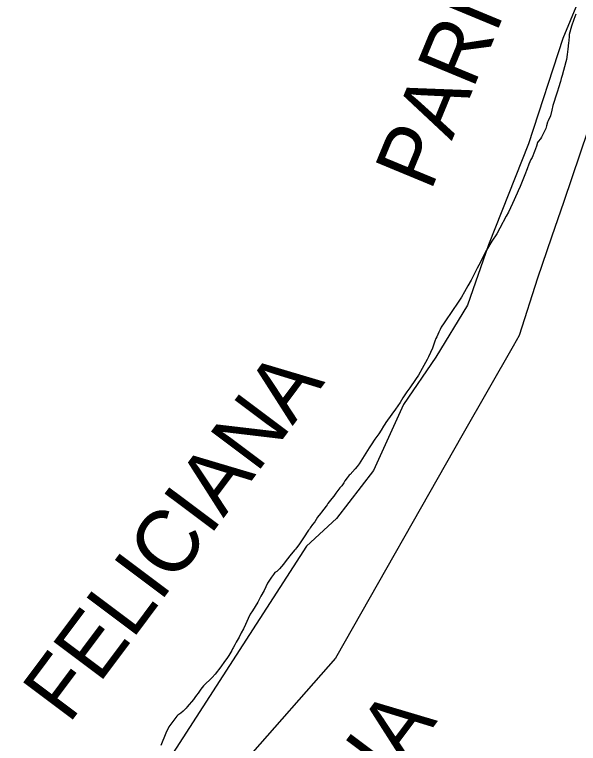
# Model space of a CAD drawing. Extents: x 3177385 to 3215275, y 903885 to 929304.
# Drawn here: x 3182527 to 3183436, y 916526 to 917702 of the extents above; entities that cross this region are included whole.
import ezdxf

# ---------------------------------------------------------------- set-up
doc = ezdxf.new("R2010")
doc.units = 0
for name, color, linetype in [('V-SITE-VEGE', 7, 'Continuous'), ('V-TOPO-BNDY', 7, 'Continuous'), ('V-TOPO-GNAM-IDEN', 7, 'Continuous'), ('V-TOPO-SHOR', 7, 'Continuous')]:
    doc.layers.add(name, color=color, linetype=linetype)

msp = doc.modelspace()

# ---------------------------------------------------------------- linework, layer by layer
at = {"layer": 'V-SITE-VEGE'}
for p, q in [((3183428.9, 917693.5), (3183425.2, 917682.7)), ((3183431.8, 917702.3), (3183428.9, 917693.5)), ((3183425.2, 917682.7), (3183421.4, 917669.5)), ((3183421.4, 917669.5), (3183421, 917666.7)), ((3183420.4, 917656.3), (3183419.1, 917645.9)), ((3183420.5, 917659.1), (3183420.4, 917656.3)), ((3183421, 917666.7), (3183420.5, 917659.1)), ((3183419.1, 917645.9), (3183417.8, 917637.1)), ((3183417.8, 917637.1), (3183416.9, 917629.1)), ((3183416, 917625.5), (3183410.2, 917603.5)), ((3183416.9, 917629.1), (3183416, 917625.5)), ((3183408.5, 917598.7), (3183407.2, 917593.9)), ((3183410.2, 917603.5), (3183408.5, 917598.7)), ((3183407.2, 917593.9), (3183403.9, 917583.5)), ((3183401.4, 917574.8), (3183395.1, 917554.8)), ((3183402.6, 917578.3), (3183401.4, 917574.8)), ((3183403.9, 917583.5), (3183402.6, 917578.3)), ((3183395.1, 917554.8), (3183393.4, 917547.6)), ((3183390.9, 917538.4), (3183387.2, 917530.4)), ((3183393.4, 917547.6), (3183390.9, 917538.4)), ((3183386.4, 917528), (3183384.7, 917522)), ((3183387.2, 917530.4), (3183386.4, 917528)), ((3183383.4, 917518), (3183376.8, 917504.1)), ((3183384.7, 917522), (3183383.4, 917518)), ((3183376.8, 917504.1), (3183375.2, 917501.3)), ((3183370.3, 917495.4), (3183368.6, 917489.4)), ((3183371.5, 917496.9), (3183370.3, 917495.4)), ((3183375.2, 917501.3), (3183371.5, 917496.9)), ((3183365.3, 917480.6), (3183361.6, 917471.4)), ((3183368.6, 917489.4), (3183365.3, 917480.6)), ((3183359.5, 917467.8), (3183357.9, 917464.2)), ((3183361.6, 917471.4), (3183359.5, 917467.8)), ((3183356.2, 917460.2), (3183353.7, 917452.7)), ((3183357.9, 917464.2), (3183356.2, 917460.2)), ((3183353.7, 917452.7), (3183350, 917443.1)), ((3183350, 917443.1), (3183342.2, 917424.7)), ((3183342.2, 917424.7), (3183338.9, 917417.6)), ((3183337.2, 917413.6), (3183329.8, 917396.8)), ((3183338.9, 917417.6), (3183337.2, 917413.6)), ((3183329.8, 917396.8), (3183323.2, 917382.9)), ((3183319.5, 917376.5), (3183309.6, 917357.4)), ((3183323.2, 917382.9), (3183319.5, 917376.5)), ((3183309.6, 917357.4), (3183304.3, 917348.2)), ((3183304.3, 917348.2), (3183296.6, 917336.3)), ((3183296.6, 917336.3), (3183288, 917322)), ((3183288, 917322), (3183275.6, 917297.7)), ((3183273.1, 917292.5), (3183267.4, 917282.1)), ((3183275.6, 917297.7), (3183273.1, 917292.5)), ((3183267.4, 917282.1), (3183262.9, 917273.4)), ((3183262.9, 917273.4), (3183257.6, 917264.2)), ((3183257.6, 917264.2), (3183252.6, 917254.7)), ((3183247.3, 917245.9), (3183245.3, 917242.7)), ((3183252.6, 917254.7), (3183247.3, 917245.9)), ((3183242, 917238), (3183222, 917207.7)), ((3183245.3, 917242.7), (3183242, 917238)), ((3183215, 917197.8), (3183213.4, 917193.8)), ((3183219.5, 917204.6), (3183215, 917197.8)), ((3183222, 917207.7), (3183219.5, 917204.6)), ((3183210.9, 917189.8), (3183208, 917182.2)), ((3183213.4, 917193.8), (3183210.9, 917189.8)), ((3183204.7, 917175.1), (3183200.6, 917163.9)), ((3183206.4, 917179.1), (3183204.7, 917175.1)), ((3183208, 917182.2), (3183206.4, 917179.1)), ((3183200.6, 917163.9), (3183194.4, 917149.9)), ((3183192.3, 917145.6), (3183184.1, 917130.8)), ((3183194.4, 917149.9), (3183192.3, 917145.6)), ((3183184.1, 917130.8), (3183178, 917120.5)), ((3183178, 917120.5), (3183173.1, 917113.3)), ((3183173.1, 917113.3), (3183164.1, 917099.8)), ((3183159.2, 917093.1), (3183153.1, 917083.5)), ((3183164.1, 917099.8), (3183159.2, 917093.1)), ((3183151, 917079.9), (3183148.5, 917075.9)), ((3183153.1, 917083.5), (3183151, 917079.9)), ((3183148.5, 917075.9), (3183141.2, 917065.2)), ((3183135.1, 917057.3), (3183125.7, 917043.8)), ((3183141.2, 917065.2), (3183135.1, 917057.3)), ((3183122, 917038.2), (3183117.9, 917031.8)), ((3183124.1, 917041), (3183122, 917038.2)), ((3183125.7, 917043.8), (3183124.1, 917041)), ((3183114.2, 917025.9), (3183107.7, 917017.1)), ((3183117.9, 917031.8), (3183114.2, 917025.9)), ((3183107.7, 917017.1), (3183101.6, 917008)), ((3183098.7, 917003.2), (3183082.4, 916977.3)), ((3183101.6, 917008), (3183098.7, 917003.2)), ((3183082.4, 916977.3), (3183079.1, 916973)), ((3183076.2, 916969.4), (3183068.1, 916960.3)), ((3183079.1, 916973), (3183076.2, 916969.4)), ((3183063.2, 916954.7), (3183059.6, 916950)), ((3183064.5, 916957.1), (3183063.2, 916954.7)), ((3183066.1, 916959.1), (3183064.5, 916957.1)), ((3183068.1, 916960.3), (3183066.1, 916959.1)), ((3183054.7, 916942), (3183051.4, 916938.4)), ((3183057.5, 916946.4), (3183054.7, 916942)), ((3183059.6, 916950), (3183057.5, 916946.4)), ((3183044.9, 916930.1), (3183041.6, 916925.3)), ((3183051.4, 916938.4), (3183044.9, 916930.1)), ((3183034.3, 916915.8), (3183032.2, 916913.4)), ((3183038.4, 916921.4), (3183034.3, 916915.8)), ((3183041.6, 916925.3), (3183038.4, 916921.4)), ((3183029, 916909), (3183021.6, 916899.5)), ((3183030.6, 916911), (3183029, 916909)), ((3183032.2, 916913.4), (3183030.6, 916911)), ((3183020, 916897.1), (3183015.5, 916891.2)), ((3183021.6, 916899.5), (3183020, 916897.1)), ((3183011, 916884), (3183007.4, 916879.3)), ((3183015.5, 916891.2), (3183011, 916884)), ((3183000.8, 916870.1), (3182998.4, 916866.9)), ((3183002.1, 916872.1), (3183000.8, 916870.1)), ((3183003.7, 916874.1), (3183002.1, 916872.1)), ((3183007.4, 916879.3), (3183003.7, 916874.1)), ((3182995.1, 916861.4), (3182984.9, 916846.7)), ((3182998.4, 916866.9), (3182995.1, 916861.4)), ((3182984.9, 916846.7), (3182981.2, 916841.9)), ((3182978.4, 916838.3), (3182970.6, 916828.8)), ((3182980, 916839.9), (3182978.4, 916838.3)), ((3182981.2, 916841.9), (3182980, 916839.9)), ((3182970.6, 916828.8), (3182963.3, 916819.3)), ((3182960.5, 916815.3), (3182953.9, 916807.8)), ((3182963.3, 916819.3), (3182960.5, 916815.3)), ((3182944.2, 916798.7), (3182941.3, 916794.7)), ((3182945.4, 916800.6), (3182944.2, 916798.7)), ((3182946.7, 916802.2), (3182945.4, 916800.6)), ((3182949.5, 916803.8), (3182946.7, 916802.2)), ((3182951.1, 916805.4), (3182949.5, 916803.8)), ((3182953.9, 916807.8), (3182951.1, 916805.4)), ((3182941.3, 916794.7), (3182934.8, 916784.7)), ((3182934.8, 916784.7), (3182929.1, 916773.2)), ((3182923.7, 916764), (3182918.8, 916754.5)), ((3182929.1, 916773.2), (3182923.7, 916764)), ((3182918.8, 916754.5), (3182910.2, 916740.1)), ((3182910.2, 916740.1), (3182906.9, 916735)), ((3182903.2, 916727.8), (3182899.1, 916718.2)), ((3182906.9, 916735), (3182903.2, 916727.8)), ((3182899.1, 916718.2), (3182895.8, 916711.1)), ((3182892.1, 916704.7), (3182888.8, 916697.9)), ((3182895.8, 916711.1), (3182892.1, 916704.7)), ((3182888.8, 916697.9), (3182884.3, 916689.9)), ((3182879.4, 916680.8), (3182878.2, 916678.8)), ((3182881.8, 916685.2), (3182879.4, 916680.8)), ((3182884.3, 916689.9), (3182881.8, 916685.2)), ((3182873.6, 916670.8), (3182872.4, 916668.4)), ((3182876.9, 916676.4), (3182873.6, 916670.8)), ((3182878.2, 916678.8), (3182876.9, 916676.4)), ((3182865.5, 916658.5), (3182859.4, 916650.2)), ((3182869.1, 916663.3), (3182865.5, 916658.5)), ((3182872.4, 916668.4), (3182869.1, 916663.3)), ((3182859.4, 916650.2), (3182850, 916637.9)), ((3182850, 916637.9), (3182845.1, 916632.7)), ((3182845.1, 916632.7), (3182831.3, 916619.2)), ((3182827.2, 916614.1), (3182822.7, 916607.7)), ((3182831.3, 916619.2), (3182827.2, 916614.1)), ((3182817.4, 916600.6), (3182815, 916597.4)), ((3182819.9, 916604.2), (3182817.4, 916600.6)), ((3182822.7, 916607.7), (3182819.9, 916604.2)), ((3182815, 916597.4), (3182805.2, 916585.5)), ((3182794.7, 916575.2), (3182790.2, 916572)), ((3182798.3, 916578.4), (3182794.7, 916575.2)), ((3182803.2, 916583.1), (3182798.3, 916578.4)), ((3182805.2, 916585.5), (3182803.2, 916583.1)), ((3182788.6, 916570.5), (3182775.5, 916553.4)), ((3182790.2, 916572), (3182788.6, 916570.5)), ((3182775.5, 916553.4), (3182770.6, 916543)), ((3182770.6, 916543), (3182762.7, 916523.1))]:
    msp.add_line(p, q, dxfattribs=at)
at = {"layer": 'V-TOPO-BNDY'}
for p, q in [((3183559.2, 917836.9), (3183412.9, 917400.3)), ((3183412.9, 917400.3), (3183393, 917342.8)), ((3183393, 917342.8), (3183370.4, 917276.9)), ((3183370.4, 917276.9), (3183340.5, 917184.4)), ((3183340.5, 917184.4), (3183330.7, 917167.2)), ((3183330.7, 917167.2), (3183250.1, 917026.2)), ((3183250.1, 917026.2), (3183044.2, 916663.7)), ((3183044.2, 916663.7), (3182752.8, 916333.9))]:
    msp.add_line(p, q, dxfattribs=at)
at = {"layer": 'V-TOPO-SHOR'}
msp.add_lwpolyline([(3183482, 917834.3), (3183411.1, 917662.8), (3183355.4, 917493.3), (3183291.1, 917330.4), (3183257.1, 917233.3), (3183206, 917149.4), (3183153.8, 917073.1), (3183105.6, 916966.4), (3183045.8, 916889.2), (3182997.4, 916844.3), (3182371, 915874.8)], dxfattribs=at)

# ---------------------------------------------------------------- texts
at = {"layer": 'V-TOPO-GNAM-IDEN'}
for s, rotation, p in [('PARISH', 67.5014, (3183197.7, 917415)), ('FELICIANA', 53.1586, (3182614, 916556.2)), ('CONCORDIA', 53.1586, (3182719.8, 915909))]:
    msp.add_text(s, height=100, rotation=rotation, dxfattribs=at).set_placement(p)

doc.saveas('drawing.dxf')
